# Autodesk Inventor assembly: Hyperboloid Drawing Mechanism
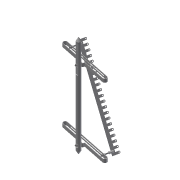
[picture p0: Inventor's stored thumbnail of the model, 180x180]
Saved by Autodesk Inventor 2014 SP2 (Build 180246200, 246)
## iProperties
Created: 2015-04
Part Number: Hyperboloid Drawing Mechanism
Document SubType Name: Assembly
Designer: SFC
Author: SFC
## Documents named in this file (9)
- D:\SFC\3-Autodesk\2014-01-30 GrabCAD\23 - Mecanism trasare hiperboloid\Hyperboloid Drawing Mechanism.iam
- D:\SFC\3-Autodesk\2014-01-30 GrabCAD\23 - Mecanism trasare hiperboloid\Multi-hole plate.ipt
- D:\SFC\3-Autodesk\2014-01-30 GrabCAD\23 - Mecanism trasare hiperboloid\Threaded rod.ipt
- D:\SFC\3-Autodesk\2014-01-30 GrabCAD\23 - Mecanism trasare hiperboloid\Pin.ipt
- D:\SFC\3-Autodesk\2014-01-30 GrabCAD\23 - Mecanism trasare hiperboloid\Central Shaft.ipt
- D:\SFC\3-Autodesk\2014-01-30 GrabCAD\23 - Mecanism trasare hiperboloid\Adjustable Stand.ipt
- C:\Users\SFC\Documents\Inventor\Content Center Files\R2014\en-US\ISO 7045  H\ISO 7045 - M6 x 30 - 4.8 - HISO.ipt
- C:\Users\SFC\Documents\Inventor\Content Center Files\R2014\en-US\ISO 7090\ISO 7090 - 6 - 140 HV(1).ipt
- C:\Users\SFC\Documents\Inventor\Content Center Files\R2014\en-US\ISO 4032(2)\ISO 4032 - M6ISO.ipt
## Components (22 placed, 8 different names)
1. Multi-hole plate:1 — Insert:2, Angle:2, Mate:18, Mate:19
2. Threaded rod:1 — Insert:3, Mate:13, Mate:15, Mate:17, Mate:18, Mate:19
3. Threaded rod:2 — Insert:2, Insert:4, Mate:14, Flush:2, Mate:16
4. Pin:1 — Insert:3
5. Pin:2 — Insert:4
6. Central Shaft:1 — Mate:3, Mate:4, Mate:8, Insert:5, Mate:9, Mate:11, Mate:12, Mate:15, Mate:16, Mate:21, Insert:8
7. Adjustable Stand:1 — Insert:5, Mate:9, Angle:1, Mate:14, Flush:2, Insert:7, Mate:27, Mate:29
8. Adjustable Stand:2 — Mate:11, Mate:12, Angle:1, Mate:13, Angle:2, Mate:17, Insert:6, Mate:23, Mate:25
9. ISO 7045 H M6 x 30 - 4.8 - H:1 — Insert:6, Mate:20
10. ISO 7045 H M6 x 30 - 4.8 - H:2 — Insert:7
11. ISO 7090 6 - 140 HV:1 — Mate:20, Mate:21
12. ISO 7090 6 - 140 HV:2 — Insert:8
13. ISO 4032 M6:1
14. ISO 4032 M6:2
15. ISO 7090 6 - 140 HV:3 — Mate:23
16. ISO 7090 6 - 140 HV:4 — Mate:25
17. ISO 7090 6 - 140 HV:5 — Mate:27
18. ISO 7090 6 - 140 HV:6 — Mate:29
19. ISO 4032 M6:3
20. ISO 4032 M6:4
21. ISO 4032 M6:5
22. ISO 4032 M6:6
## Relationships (29: Mate 19, Insert 7, Angle 2, Flush 1)
- Insert:2: Multi-hole plate:1 ↔ Threaded rod:2
- Mate:3: Central Shaft:1
- Mate:4: Central Shaft:1
- Mate:8: Central Shaft:1
- Insert:3: Threaded rod:1 ↔ Pin:1
- Insert:4: Threaded rod:2 ↔ Pin:2
- Insert:5: Central Shaft:1 ↔ Adjustable Stand:1
- Mate:9: Central Shaft:1 ↔ Adjustable Stand:1
- Mate:11: Central Shaft:1 ↔ Adjustable Stand:2
- Mate:12: Central Shaft:1 ↔ Adjustable Stand:2
- Angle:1: Adjustable Stand:1 ↔ Adjustable Stand:2
- Mate:13: Threaded rod:1 ↔ Adjustable Stand:2
- Mate:14: Threaded rod:2 ↔ Adjustable Stand:1
- Angle:2: Multi-hole plate:1 ↔ Adjustable Stand:2
- Flush:2: Threaded rod:2 ↔ Adjustable Stand:1
- Mate:15: Threaded rod:1 ↔ Central Shaft:1
- Mate:16: Threaded rod:2 ↔ Central Shaft:1
- Mate:17: Threaded rod:1 ↔ Adjustable Stand:2
- Mate:18: Multi-hole plate:1 ↔ Threaded rod:1
- Mate:19: Multi-hole plate:1 ↔ Threaded rod:1
- Insert:6: Adjustable Stand:2 ↔ ISO 7045 H M6 x 30 - 4.8 - H:1
- Insert:7: Adjustable Stand:1 ↔ ISO 7045 H M6 x 30 - 4.8 - H:2
- Mate:20: ISO 7045 H M6 x 30 - 4.8 - H:1 ↔ ISO 7090 6 - 140 HV:1
- Mate:21: Central Shaft:1 ↔ ISO 7090 6 - 140 HV:1
- Insert:8: Central Shaft:1 ↔ ISO 7090 6 - 140 HV:2
- Mate:23: Adjustable Stand:2 ↔ ISO 7090 6 - 140 HV:3
- Mate:25: Adjustable Stand:2 ↔ ISO 7090 6 - 140 HV:4
- Mate:27: Adjustable Stand:1 ↔ ISO 7090 6 - 140 HV:5
- Mate:29: Adjustable Stand:1 ↔ ISO 7090 6 - 140 HV:6
